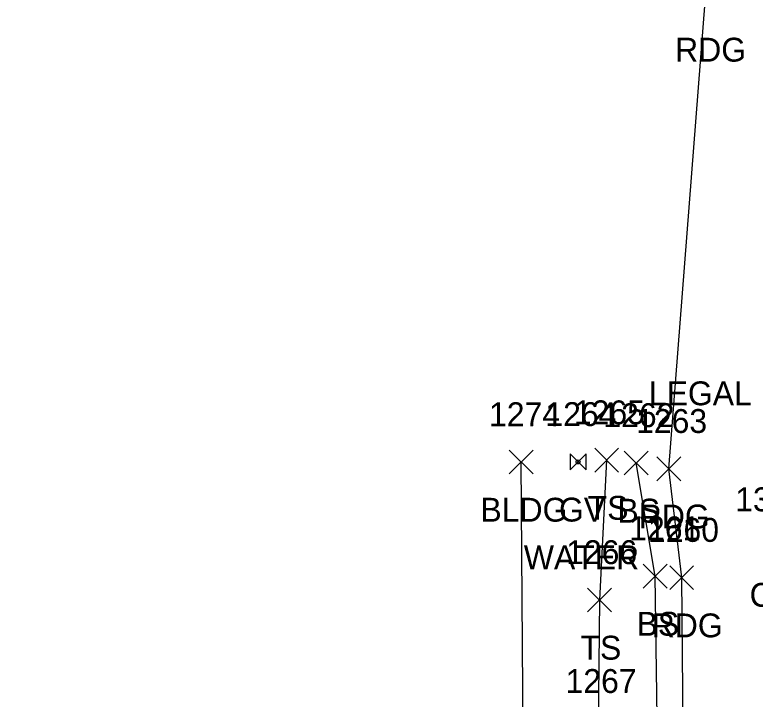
# Model space of a CAD drawing. Extents: x 1657482 to 1661439, y 647981 to 649041.
# Drawn here: x 1659744 to 1659806, y 648167.6 to 648225 of the extents above; entities that cross this region are included whole.
import ezdxf

# ---------------------------------------------------------------- set-up
doc = ezdxf.new("R2010")
doc.units = 0
for name, color, linetype in [('L_A', 7, 'Continuous'), ('L_I', 7, 'Continuous'), ('L_TIC', 7, 'Continuous'), ('LBC', 7, 'Continuous'), ('LELB', 7, 'Continuous'), ('P_A', 7, 'Continuous'), ('P_I', 7, 'Continuous'), ('P_TIC', 7, 'Continuous'), ('PEU', 7, 'Continuous'), ('S_C', 7, 'Continuous'), ('U_A', 7, 'Continuous'), ('U_C', 7, 'Continuous'), ('U_I', 7, 'Continuous'), ('UWV', 7, 'Continuous')]:
    doc.layers.add(name, color=color, linetype=linetype)

msp = doc.modelspace()

# ---------------------------------------------------------------- linework, layer by layer
at = {"layer": 'L_TIC'}
for points in [[(1659785.394, 648186.498), (1659787.394, 648188.498)], [(1659787.394, 648186.498), (1659785.394, 648188.498)], [(1659792.55, 648186.657), (1659794.55, 648188.657)], [(1659794.55, 648186.657), (1659792.55, 648188.657)], [(1659795.014, 648186.418), (1659797.014, 648188.418)], [(1659797.014, 648186.418), (1659795.014, 648188.418)], [(1659796.619, 648176.939), (1659798.619, 648178.939)], [(1659798.619, 648176.939), (1659796.619, 648178.939)], [(1659791.953, 648174.94), (1659793.953, 648176.94)], [(1659793.953, 648174.94), (1659791.953, 648176.94)]]:
    msp.add_lwpolyline(points, dxfattribs=at)
at = {"layer": 'LBC'}
msp.add_lwpolyline([(1659744.077, 648158.875), (1659743.994, 648158.097), (1659761.352, 648158.314), (1659769.22, 648158.344), (1659786.45, 648158.566), (1659786.65, 648159.231), (1659786.85, 648159.594), (1659786.592, 648160.741), (1659786.394, 648187.498)], dxfattribs=at)
at = {"layer": 'LELB'}
for points in [[(1659793.55, 648187.657), (1659792.953, 648175.94), (1659792.851, 648165.146), (1659790.768, 648160.667)], [(1659792.946, 648159.154), (1659795.065, 648159.06), (1659797.841, 648162.1), (1659797.619, 648177.939), (1659796.014, 648187.418)]]:
    msp.add_lwpolyline(points, dxfattribs=at)
at = {"layer": 'P_TIC'}
for points in [[(1659797.755, 648185.929), (1659799.755, 648187.929)], [(1659799.755, 648185.929), (1659797.755, 648187.929)], [(1659798.835, 648176.806), (1659800.835, 648178.806)], [(1659800.835, 648176.806), (1659798.835, 648178.806)]]:
    msp.add_lwpolyline(points, dxfattribs=at)
at = {"layer": 'PEU'}
msp.add_lwpolyline([(1659797.276, 648121.743), (1659797.87, 648123.934), (1659798.337, 648135.506), (1659799.277, 648146.42), (1659799.999, 648161.861), (1659799.835, 648177.806), (1659798.755, 648186.929), (1659801.799, 648226.041), (1659802.332, 648244.746), (1659801.134, 648257.962), (1659801.986, 648290.642), (1659800.919, 648322.82)], dxfattribs=at)
at = {"layer": 'UWV'}
for p, q in [((1659790.492, 648188.175), (1659791.826, 648186.842)), ((1659791.826, 648188.175), (1659790.492, 648186.842))]:
    msp.add_line(p, q, dxfattribs=at)
for points in [[(1659790.492, 648188.175), (1659790.492, 648186.842)], [(1659791.826, 648186.842), (1659791.826, 648188.175)]]:
    msp.add_lwpolyline(points, dxfattribs=at)
msp.add_circle((1659791.159, 648187.508), 0.167, dxfattribs=at)

# ---------------------------------------------------------------- texts
at = {"layer": 'L_A'}
for s, p in [('BLDG', (1659782.984, 648182.498)), ('TS', (1659791.96, 648182.657)), ('BS', (1659794.455, 648182.418)), ('BS', (1659796.06, 648172.939)), ('TS', (1659791.362, 648170.94))]:
    msp.add_text(s, height=2, dxfattribs=at).set_placement(p)
at = {"layer": 'L_I'}
for s, p in [('1274', (1659783.701, 648190.498)), ('1265', (1659790.81, 648190.657)), ('1262', (1659793.274, 648190.418)), ('1261', (1659795.446, 648180.939)), ('1266', (1659790.158, 648178.94)), ('1267', (1659790.111, 648168.146))]:
    msp.add_text(s, height=2, dxfattribs=at).set_placement(p)
at = {"layer": 'P_A'}
for s, p in [('RDG', (1659799.287, 648221.041)), ('RDG', (1659796.243, 648181.929)), ('CR', (1659805.522, 648175.369)), ('RDG', (1659797.323, 648172.806))]:
    msp.add_text(s, height=2, dxfattribs=at).set_placement(p)
at = {"layer": 'P_I'}
for s, p in [('1263', (1659796.015, 648189.929)), ('1303', (1659804.318, 648183.369)), ('1260', (1659797.008, 648180.806))]:
    msp.add_text(s, height=2, dxfattribs=at).set_placement(p)
at = {"layer": 'S_C'}
msp.add_text('LEGAL LOAD LIMIT 24000 POUNDS', height=2, dxfattribs=at).set_placement((1659797.084, 648192.25))
at = {"layer": 'U_A'}
msp.add_text('GV', height=2, dxfattribs=at).set_placement((1659789.561, 648182.508))
at = {"layer": 'U_C'}
msp.add_text('WATER', height=2, dxfattribs=at).set_placement((1659786.616, 648178.508))
at = {"layer": 'U_I'}
msp.add_text('1264', height=2, dxfattribs=at).set_placement((1659788.419, 648190.508))

doc.saveas('drawing.dxf')
